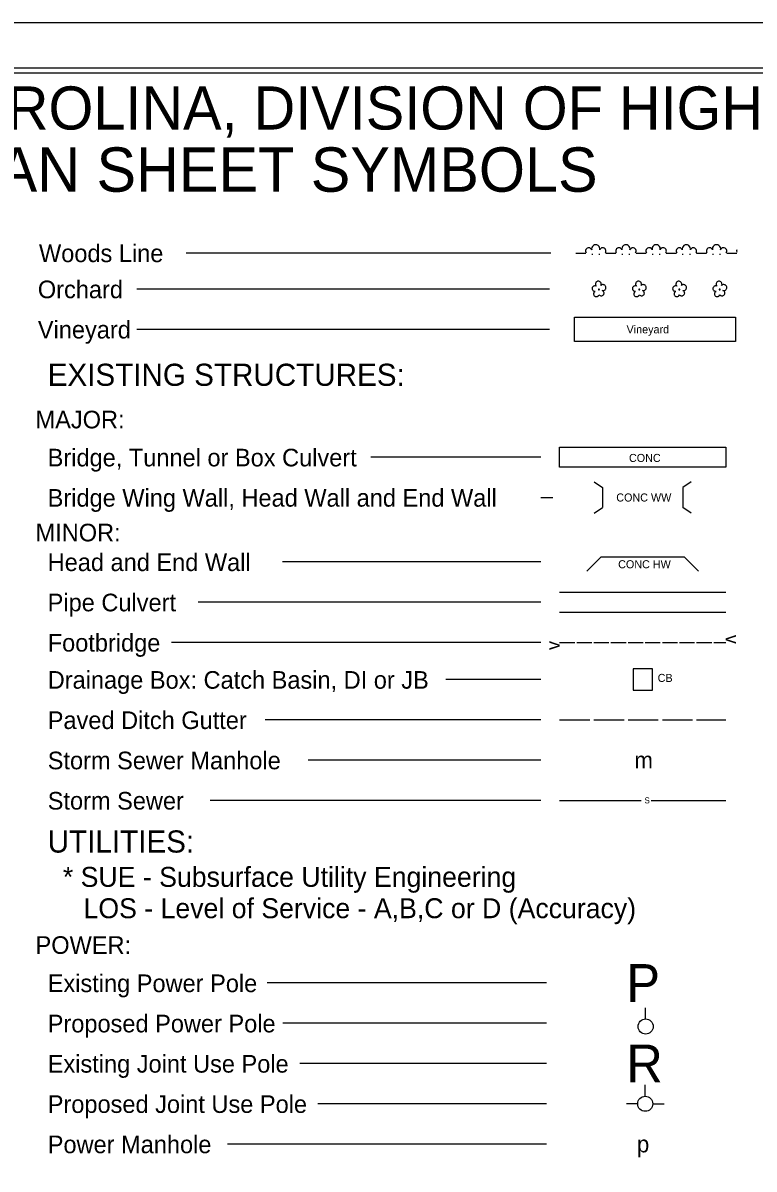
# Model space of a CAD drawing. Extents: x 1669394 to 1671078, y 697867 to 698967.
# Drawn here: x 1670317 to 1670680, y 698398 to 698967 of the extents above; entities that cross this region are included whole.
import ezdxf

# ---------------------------------------------------------------- set-up
doc = ezdxf.new("R2010")
doc.units = 0
for name, color, linetype in [('Sheet Cutting Line CELL', 7, 'Continuous'), ('Sheet Plot Border Inside CELL', 7, 'Continuous'), ('Sheet Plot Border Outside CELL', 7, 'Continuous'), ('Sheet Symbology CELL', 7, 'Continuous')]:
    doc.layers.add(name, color=color, linetype=linetype)

msp = doc.modelspace()

# ---------------------------------------------------------------- linework, layer by layer
at = {"layer": 'Sheet Cutting Line CELL'}
msp.add_line((1671077.79, 698967.01), (1669393.79, 698967.01), dxfattribs=at)
at = {"layer": 'Sheet Plot Border Inside CELL'}
msp.add_lwpolyline([(1669406.79, 697889.46), (1671073.29, 697889.46), (1671073.29, 698944.56), (1669406.79, 698944.56)], close=True, dxfattribs=at)
at = {"layer": 'Sheet Plot Border Outside CELL'}
msp.add_lwpolyline([(1669393.79, 697867.01), (1671077.79, 697867.01), (1671077.79, 698967.01), (1669393.79, 698967.01)], close=True, dxfattribs=at)
at = {"layer": 'Sheet Symbology CELL'}
for p, q in [((1670579.06, 698852.74), (1670397.93, 698852.74)), ((1670591.45, 698852.74), (1670596.45, 698852.74)), ((1670599.4, 698852.24), (1670599.9, 698852.24)), ((1670602.9, 698852.24), (1670603.4, 698852.24)), ((1670606.45, 698852.74), (1670611.45, 698852.74)), ((1670614.4, 698852.24), (1670614.9, 698852.24)), ((1670617.9, 698852.24), (1670618.4, 698852.24)), ((1670621.45, 698852.74), (1670626.45, 698852.74)), ((1670629.4, 698852.24), (1670629.9, 698852.24)), ((1670632.9, 698852.24), (1670633.4, 698852.24)), ((1670636.45, 698852.74), (1670641.45, 698852.74)), ((1670644.4, 698852.24), (1670644.9, 698852.24)), ((1670647.9, 698852.24), (1670648.4, 698852.24)), ((1670651.45, 698852.74), (1670656.45, 698852.74)), ((1670659.4, 698852.24), (1670659.9, 698852.24)), ((1670662.9, 698852.24), (1670663.4, 698852.24)), ((1670666.45, 698852.74), (1670671.45, 698852.74)), ((1670578.49, 698834.82), (1670373.55, 698834.82)), ((1670578.49, 698814.82), (1670373.55, 698814.82)), ((1670574.18, 698751.31), (1670489.75, 698751.31)), ((1670600.63, 698739.17), (1670604.73, 698736.31)), ((1670604.73, 698736.31), (1670604.73, 698726.31)), ((1670648.83, 698739.17), (1670644.73, 698736.31)), ((1670644.73, 698736.31), (1670644.73, 698726.31)), ((1670574.18, 698731.31), (1670580.16, 698731.31)), ((1670600.63, 698723.45), (1670604.73, 698726.31)), ((1670648.83, 698723.45), (1670644.73, 698726.31)), ((1670597.03, 698694.74), (1670604.1, 698701.82)), ((1670604.1, 698701.82), (1670645.35, 698701.82)), ((1670645.35, 698701.82), (1670652.43, 698694.74)), ((1670574.18, 698699.32), (1670445.88, 698699.32)), ((1670583.48, 698684.32), (1670665.98, 698684.32)), ((1670574.18, 698679.32), (1670403.99, 698679.32)), ((1670583.48, 698674.32), (1670665.98, 698674.32)), ((1670574.18, 698659.32), (1670390.7, 698659.32)), ((1670583.48, 698659.32), (1670590.98, 698659.32)), ((1670591.98, 698659.32), (1670599.48, 698659.32)), ((1670600.48, 698659.32), (1670607.98, 698659.32)), ((1670608.98, 698659.32), (1670616.48, 698659.32)), ((1670617.48, 698659.32), (1670624.98, 698659.32)), ((1670625.98, 698659.32), (1670633.48, 698659.32)), ((1670634.48, 698659.32), (1670641.98, 698659.32)), ((1670642.98, 698659.32), (1670650.48, 698659.32)), ((1670651.48, 698659.32), (1670658.98, 698659.32)), ((1670659.98, 698659.32), (1670665.98, 698659.32)), ((1670574.18, 698640.88), (1670526.98, 698640.88)), ((1670574.18, 698620.88), (1670437.23, 698620.88)), ((1670583.48, 698620.88), (1670598.48, 698620.88)), ((1670600.48, 698620.88), (1670615.48, 698620.88)), ((1670617.48, 698620.88), (1670632.48, 698620.88)), ((1670634.48, 698620.88), (1670649.48, 698620.88)), ((1670651.48, 698620.88), (1670665.98, 698620.88)), ((1670574.18, 698600.88), (1670458.5, 698600.88)), ((1670574.18, 698580.88), (1670409.98, 698580.88)), ((1670583.48, 698580.88), (1670624, 698580.88)), ((1670629, 698580.88), (1670665.98, 698580.88)), ((1670576.96, 698490.2), (1670438.26, 698490.2)), ((1670626.19, 698472.31), (1670626.19, 698477.93)), ((1670576.96, 698470.2), (1670446.05, 698470.2)), ((1670576.96, 698450.2), (1670454.45, 698450.2)), ((1670625.98, 698433.96), (1670625.98, 698439.58)), ((1670576.96, 698430.2), (1670463.45, 698430.2)), ((1670622.23, 698430.21), (1670616.6, 698430.21)), ((1670629.73, 698430.21), (1670635.35, 698430.21)), ((1670576.96, 698410.2), (1670418.46, 698410.2))]:
    msp.add_line(p, q, dxfattribs=at)
for points in [[(1671060.79, 698942.01), (1669560.79, 698942.01), (1669560.79, 697893.03), (1671060.79, 697893.03)], [(1670619.91, 698635.57), (1670629.53, 698635.57), (1670629.53, 698646.2), (1670619.91, 698646.2)]]:
    msp.add_lwpolyline(points, close=True, dxfattribs=at)
for points in [[(1670603.93, 698836.57), (1670604.08, 698836.87), (1670604.13, 698837.17), (1670604.08, 698837.47), (1670604.03, 698837.77), (1670603.88, 698838.02), (1670603.73, 698838.27), (1670603.48, 698838.47), (1670603.23, 698838.62), (1670602.88, 698838.72), (1670602.63, 698838.72), (1670602.33, 698838.67), (1670602.03, 698838.57), (1670601.78, 698838.42), (1670601.53, 698838.22), (1670601.38, 698837.92), (1670601.28, 698837.67), (1670601.23, 698837.37), (1670601.23, 698837.07), (1670601.28, 698836.77), (1670601.43, 698836.52), (1670601.63, 698836.22), (1670601.38, 698836.37), (1670601.08, 698836.42), (1670600.78, 698836.42), (1670600.53, 698836.32), (1670600.28, 698836.22), (1670600.03, 698836.02), (1670599.83, 698835.82), (1670599.68, 698835.57), (1670599.63, 698835.32), (1670599.58, 698834.97), (1670599.63, 698834.72), (1670599.73, 698834.47), (1670599.93, 698834.22), (1670600.08, 698834.02), (1670600.33, 698833.87), (1670600.63, 698833.72), (1670600.88, 698833.67), (1670601.18, 698833.67), (1670600.93, 698833.57), (1670600.68, 698833.37), (1670600.53, 698833.17), (1670600.43, 698832.87), (1670600.33, 698832.57), (1670600.33, 698832.32), (1670600.38, 698832.02), (1670600.53, 698831.77), (1670600.68, 698831.52), (1670600.88, 698831.32), (1670601.13, 698831.17), (1670601.38, 698831.07), (1670601.68, 698831.07), (1670601.98, 698831.07), (1670602.23, 698831.12), (1670602.48, 698831.32), (1670602.73, 698831.47), (1670602.98, 698831.92)], [(1670623.93, 698836.57), (1670624.08, 698836.87), (1670624.13, 698837.17), (1670624.08, 698837.47), (1670624.03, 698837.77), (1670623.88, 698838.02), (1670623.73, 698838.27), (1670623.48, 698838.47), (1670623.23, 698838.62), (1670622.88, 698838.72), (1670622.63, 698838.72), (1670622.33, 698838.67), (1670622.03, 698838.57), (1670621.78, 698838.42), (1670621.53, 698838.22), (1670621.38, 698837.92), (1670621.28, 698837.67), (1670621.23, 698837.37), (1670621.23, 698837.07), (1670621.28, 698836.77), (1670621.43, 698836.52), (1670621.63, 698836.22), (1670621.38, 698836.37), (1670621.08, 698836.42), (1670620.78, 698836.42), (1670620.53, 698836.32), (1670620.28, 698836.22), (1670620.03, 698836.02), (1670619.83, 698835.82), (1670619.68, 698835.57), (1670619.63, 698835.32), (1670619.58, 698834.97), (1670619.63, 698834.72), (1670619.73, 698834.47), (1670619.93, 698834.22), (1670620.08, 698834.02), (1670620.33, 698833.87), (1670620.63, 698833.72), (1670620.88, 698833.67), (1670621.18, 698833.67), (1670620.93, 698833.57), (1670620.68, 698833.37), (1670620.53, 698833.17), (1670620.43, 698832.87), (1670620.33, 698832.57), (1670620.33, 698832.32), (1670620.38, 698832.02), (1670620.53, 698831.77), (1670620.68, 698831.52), (1670620.88, 698831.32), (1670621.13, 698831.17), (1670621.38, 698831.07), (1670621.68, 698831.07), (1670621.98, 698831.07), (1670622.23, 698831.12), (1670622.48, 698831.32), (1670622.73, 698831.47), (1670622.98, 698831.92)], [(1670643.93, 698836.57), (1670644.08, 698836.87), (1670644.13, 698837.17), (1670644.08, 698837.47), (1670644.03, 698837.77), (1670643.88, 698838.02), (1670643.73, 698838.27), (1670643.48, 698838.47), (1670643.23, 698838.62), (1670642.88, 698838.72), (1670642.63, 698838.72), (1670642.33, 698838.67), (1670642.03, 698838.57), (1670641.78, 698838.42), (1670641.53, 698838.22), (1670641.38, 698837.92), (1670641.28, 698837.67), (1670641.23, 698837.37), (1670641.23, 698837.07), (1670641.28, 698836.77), (1670641.43, 698836.52), (1670641.63, 698836.22), (1670641.38, 698836.37), (1670641.08, 698836.42), (1670640.78, 698836.42), (1670640.53, 698836.32), (1670640.28, 698836.22), (1670640.03, 698836.02), (1670639.83, 698835.82), (1670639.68, 698835.57), (1670639.63, 698835.32), (1670639.58, 698834.97), (1670639.63, 698834.72), (1670639.73, 698834.47), (1670639.93, 698834.22), (1670640.08, 698834.02), (1670640.33, 698833.87), (1670640.63, 698833.72), (1670640.88, 698833.67), (1670641.18, 698833.67), (1670640.93, 698833.57), (1670640.68, 698833.37), (1670640.53, 698833.17), (1670640.43, 698832.87), (1670640.33, 698832.57), (1670640.33, 698832.32), (1670640.38, 698832.02), (1670640.53, 698831.77), (1670640.68, 698831.52), (1670640.88, 698831.32), (1670641.13, 698831.17), (1670641.38, 698831.07), (1670641.68, 698831.07), (1670641.98, 698831.07), (1670642.23, 698831.12), (1670642.48, 698831.32), (1670642.73, 698831.47), (1670642.98, 698831.92)], [(1670663.93, 698836.57), (1670664.08, 698836.87), (1670664.13, 698837.17), (1670664.08, 698837.47), (1670664.03, 698837.77), (1670663.88, 698838.02), (1670663.73, 698838.27), (1670663.48, 698838.47), (1670663.23, 698838.62), (1670662.88, 698838.72), (1670662.63, 698838.72), (1670662.33, 698838.67), (1670662.03, 698838.57), (1670661.78, 698838.42), (1670661.53, 698838.22), (1670661.38, 698837.92), (1670661.28, 698837.67), (1670661.23, 698837.37), (1670661.23, 698837.07), (1670661.28, 698836.77), (1670661.43, 698836.52), (1670661.63, 698836.22), (1670661.38, 698836.37), (1670661.08, 698836.42), (1670660.78, 698836.42), (1670660.53, 698836.32), (1670660.28, 698836.22), (1670660.03, 698836.02), (1670659.83, 698835.82), (1670659.68, 698835.57), (1670659.63, 698835.32), (1670659.58, 698834.97), (1670659.63, 698834.72), (1670659.73, 698834.47), (1670659.93, 698834.22), (1670660.08, 698834.02), (1670660.33, 698833.87), (1670660.63, 698833.72), (1670660.88, 698833.67), (1670661.18, 698833.67), (1670660.93, 698833.57), (1670660.68, 698833.37), (1670660.53, 698833.17), (1670660.43, 698832.87), (1670660.33, 698832.57), (1670660.33, 698832.32), (1670660.38, 698832.02), (1670660.53, 698831.77), (1670660.68, 698831.52), (1670660.88, 698831.32), (1670661.13, 698831.17), (1670661.38, 698831.07), (1670661.68, 698831.07), (1670661.98, 698831.07), (1670662.23, 698831.12), (1670662.48, 698831.32), (1670662.73, 698831.47), (1670662.98, 698831.92)], [(1670603.08, 698834.82), (1670602.93, 698834.82), (1670602.83, 698834.77), (1670602.73, 698834.72), (1670602.73, 698834.57), (1670602.73, 698834.47), (1670602.83, 698834.37), (1670602.98, 698834.37), (1670603.08, 698834.37), (1670603.18, 698834.47), (1670603.23, 698834.62), (1670603.18, 698834.72), (1670603.08, 698834.82)], [(1670602.98, 698831.92), (1670603.58, 698831.57), (1670603.88, 698831.47), (1670604.18, 698831.42), (1670604.48, 698831.47), (1670604.73, 698831.57), (1670604.98, 698831.72), (1670605.23, 698831.92), (1670605.38, 698832.17), (1670605.48, 698832.42), (1670605.58, 698832.72), (1670605.53, 698833.02), (1670605.48, 698833.32), (1670605.28, 698833.62), (1670605.13, 698833.82), (1670604.88, 698833.97), (1670604.58, 698834.12), (1670604.88, 698834.07), (1670605.23, 698834.07), (1670605.48, 698834.17), (1670605.78, 698834.32), (1670606.03, 698834.47), (1670606.23, 698834.72), (1670606.38, 698835.02), (1670606.43, 698835.32), (1670606.48, 698835.62), (1670606.43, 698835.92), (1670606.33, 698836.22), (1670606.13, 698836.47), (1670605.88, 698836.72), (1670605.63, 698836.87), (1670605.33, 698836.97), (1670605.03, 698837.02), (1670604.73, 698837.02), (1670604.43, 698836.92), (1670604.18, 698836.77), (1670603.93, 698836.57)], [(1670623.08, 698834.82), (1670622.93, 698834.82), (1670622.83, 698834.77), (1670622.73, 698834.72), (1670622.73, 698834.57), (1670622.73, 698834.47), (1670622.83, 698834.37), (1670622.98, 698834.37), (1670623.08, 698834.37), (1670623.18, 698834.47), (1670623.23, 698834.62), (1670623.18, 698834.72), (1670623.08, 698834.82)], [(1670622.98, 698831.92), (1670623.58, 698831.57), (1670623.88, 698831.47), (1670624.18, 698831.42), (1670624.48, 698831.47), (1670624.73, 698831.57), (1670624.98, 698831.72), (1670625.23, 698831.92), (1670625.38, 698832.17), (1670625.48, 698832.42), (1670625.58, 698832.72), (1670625.53, 698833.02), (1670625.48, 698833.32), (1670625.28, 698833.62), (1670625.13, 698833.82), (1670624.88, 698833.97), (1670624.58, 698834.12), (1670624.88, 698834.07), (1670625.23, 698834.07), (1670625.48, 698834.17), (1670625.78, 698834.32), (1670626.03, 698834.47), (1670626.23, 698834.72), (1670626.38, 698835.02), (1670626.43, 698835.32), (1670626.48, 698835.62), (1670626.43, 698835.92), (1670626.33, 698836.22), (1670626.13, 698836.47), (1670625.88, 698836.72), (1670625.63, 698836.87), (1670625.33, 698836.97), (1670625.03, 698837.02), (1670624.73, 698837.02), (1670624.43, 698836.92), (1670624.18, 698836.77), (1670623.93, 698836.57)], [(1670643.08, 698834.82), (1670642.93, 698834.82), (1670642.83, 698834.77), (1670642.73, 698834.72), (1670642.73, 698834.57), (1670642.73, 698834.47), (1670642.83, 698834.37), (1670642.98, 698834.37), (1670643.08, 698834.37), (1670643.18, 698834.47), (1670643.23, 698834.62), (1670643.18, 698834.72), (1670643.08, 698834.82)], [(1670642.98, 698831.92), (1670643.58, 698831.57), (1670643.88, 698831.47), (1670644.18, 698831.42), (1670644.48, 698831.47), (1670644.73, 698831.57), (1670644.98, 698831.72), (1670645.23, 698831.92), (1670645.38, 698832.17), (1670645.48, 698832.42), (1670645.58, 698832.72), (1670645.53, 698833.02), (1670645.48, 698833.32), (1670645.28, 698833.62), (1670645.13, 698833.82), (1670644.88, 698833.97), (1670644.58, 698834.12), (1670644.88, 698834.07), (1670645.23, 698834.07), (1670645.48, 698834.17), (1670645.78, 698834.32), (1670646.03, 698834.47), (1670646.23, 698834.72), (1670646.38, 698835.02), (1670646.43, 698835.32), (1670646.48, 698835.62), (1670646.43, 698835.92), (1670646.33, 698836.22), (1670646.13, 698836.47), (1670645.88, 698836.72), (1670645.63, 698836.87), (1670645.33, 698836.97), (1670645.03, 698837.02), (1670644.73, 698837.02), (1670644.43, 698836.92), (1670644.18, 698836.77), (1670643.93, 698836.57)], [(1670663.08, 698834.82), (1670662.93, 698834.82), (1670662.83, 698834.77), (1670662.73, 698834.72), (1670662.73, 698834.57), (1670662.73, 698834.47), (1670662.83, 698834.37), (1670662.98, 698834.37), (1670663.08, 698834.37), (1670663.18, 698834.47), (1670663.23, 698834.62), (1670663.18, 698834.72), (1670663.08, 698834.82)], [(1670662.98, 698831.92), (1670663.58, 698831.57), (1670663.88, 698831.47), (1670664.18, 698831.42), (1670664.48, 698831.47), (1670664.73, 698831.57), (1670664.98, 698831.72), (1670665.23, 698831.92), (1670665.38, 698832.17), (1670665.48, 698832.42), (1670665.58, 698832.72), (1670665.53, 698833.02), (1670665.48, 698833.32), (1670665.28, 698833.62), (1670665.13, 698833.82), (1670664.88, 698833.97), (1670664.58, 698834.12), (1670664.88, 698834.07), (1670665.23, 698834.07), (1670665.48, 698834.17), (1670665.78, 698834.32), (1670666.03, 698834.47), (1670666.23, 698834.72), (1670666.38, 698835.02), (1670666.43, 698835.32), (1670666.48, 698835.62), (1670666.43, 698835.92), (1670666.33, 698836.22), (1670666.13, 698836.47), (1670665.88, 698836.72), (1670665.63, 698836.87), (1670665.33, 698836.97), (1670665.03, 698837.02), (1670664.73, 698837.02), (1670664.43, 698836.92), (1670664.18, 698836.77), (1670663.93, 698836.57)], [(1670590.88, 698820.82), (1670670.88, 698820.82), (1670670.88, 698808.82), (1670590.88, 698808.82), (1670590.88, 698820.82)], [(1670583.48, 698756.31), (1670665.98, 698756.31), (1670665.98, 698746.31), (1670583.48, 698746.31), (1670583.48, 698756.31)]]:
    msp.add_lwpolyline(points, dxfattribs=at)
for centre in [(1670626.19, 698468.56), (1670625.98, 698430.2)]:
    msp.add_circle(centre, 3.75, dxfattribs=at)
for centre, radius, start, end in [((1670597.9, 698853.76), 1.58, 18.435, 219.2315), ((1670601.4, 698854.76), 2.06, 345.9638, 194.0362), ((1670604.9, 698853.76), 1.58, 320.7685, 161.5651), ((1670612.9, 698853.76), 1.58, 18.435, 219.2315), ((1670616.4, 698854.76), 2.06, 345.9638, 194.0362), ((1670619.9, 698853.76), 1.58, 320.7685, 161.5651), ((1670627.9, 698853.76), 1.58, 18.435, 219.2315), ((1670631.4, 698854.76), 2.06, 345.9638, 194.0362), ((1670634.9, 698853.76), 1.58, 320.7685, 161.5651), ((1670642.9, 698853.76), 1.58, 18.435, 219.2315), ((1670646.4, 698854.76), 2.06, 345.9638, 194.0362), ((1670649.9, 698853.76), 1.58, 320.7685, 161.5651), ((1670657.9, 698853.76), 1.58, 18.435, 219.2315), ((1670661.4, 698854.76), 2.06, 345.9638, 194.0362), ((1670664.9, 698853.76), 1.58, 320.7685, 161.5651), ((1670672.9, 698853.76), 1.58, 156.251, 203.749)]:
    msp.add_arc(centre, radius, start, end, dxfattribs=at)

# ---------------------------------------------------------------- texts
for s, height, p in [('STATE OF NORTH CAROLINA, DIVISION OF HIGHWAYS', 21.419, (1670011.36, 698914.05)), ('CONVENTIONAL  PLAN SHEET SYMBOLS', 22.0323, (1670019.48, 698883.17)), ('Woods Line', 8.75, (1670324.89, 698848.22)), ('Orchard', 8.75, (1670324.33, 698830.29)), ('Vineyard', 8.75, (1670324.33, 698810.29)), ('EXISTING STRUCTURES:', 11, (1670329.21, 698786.76)), ('MAJOR:', 8.75, (1670323.19, 698765.65)), ('Bridge, Tunnel or Box Culvert', 8.75, (1670329.21, 698746.76)), ('CONC', 4, (1670617.91, 698748.95)), ('Bridge Wing Wall, Head Wall and End Wall', 8.75, (1670329.21, 698726.76)), ('MINOR:', 8.75, (1670323.19, 698709.52)), ('Head and End Wall', 8.75, (1670329.21, 698694.77)), ('Pipe Culvert', 8.75, (1670329.21, 698674.78)), ('Footbridge', 8.75, (1670329.23, 698654.78)), ('Drainage Box: Catch Basin, DI or JB', 8.75, (1670329.23, 698636.34)), ('Paved Ditch Gutter', 8.75, (1670329.23, 698616.33)), ('Storm Sewer Manhole', 8.75, (1670329.23, 698596.33)), ('m', 8.25, (1670620.6, 698596.75)), ('Storm Sewer', 8.75, (1670329.23, 698576.33)), ('S', 3, (1670625.6, 698579.38)), ('UTILITIES:', 11, (1670329.21, 698554.96)), ('POWER:', 8.75, (1670323.19, 698504.66)), ('P', 18.75, (1670616.6, 698480.82)), ('Existing Power Pole', 8.75, (1670329.23, 698485.66)), ('Proposed Power Pole', 8.75, (1670329.23, 698465.66)), ('R', 18.75, (1670616.6, 698440.82)), ('Existing Joint Use Pole', 8.75, (1670329.23, 698445.67)), ('Proposed Joint Use Pole', 8.75, (1670329.24, 698425.66)), ('Power Manhole', 8.75, (1670329.24, 698405.66)), ('p', 8.25, (1670621.85, 698406.07))]:
    msp.add_text(s, height=height, dxfattribs=at).set_placement(p)
for s, height, rotation, p in [('Vineyard', 4, 0, (1670616.71, 698812.82)), ('CONC WW', 4, 0, (1670611.6, 698729.31)), ('CONC HW', 4, 360, (1670612.53, 698696.15)), ('v', 6.6, 270.2409, (1670665.96, 698663.05)), ('v', 6.6, 89.7591, (1670583.46, 698655.58)), ('CB', 4, 360, (1670632.16, 698639.7)), ('* SUE - Subsurface Utility Engineering', 9.9, 360, (1670336.75, 698537.94)), ('LOS - Level of Service - A,B,C or D (Accuracy) ', 9.9, 360, (1670347.02, 698522.37))]:
    msp.add_text(s, height=height, rotation=rotation, dxfattribs=at).set_placement(p)

doc.saveas('drawing.dxf')
